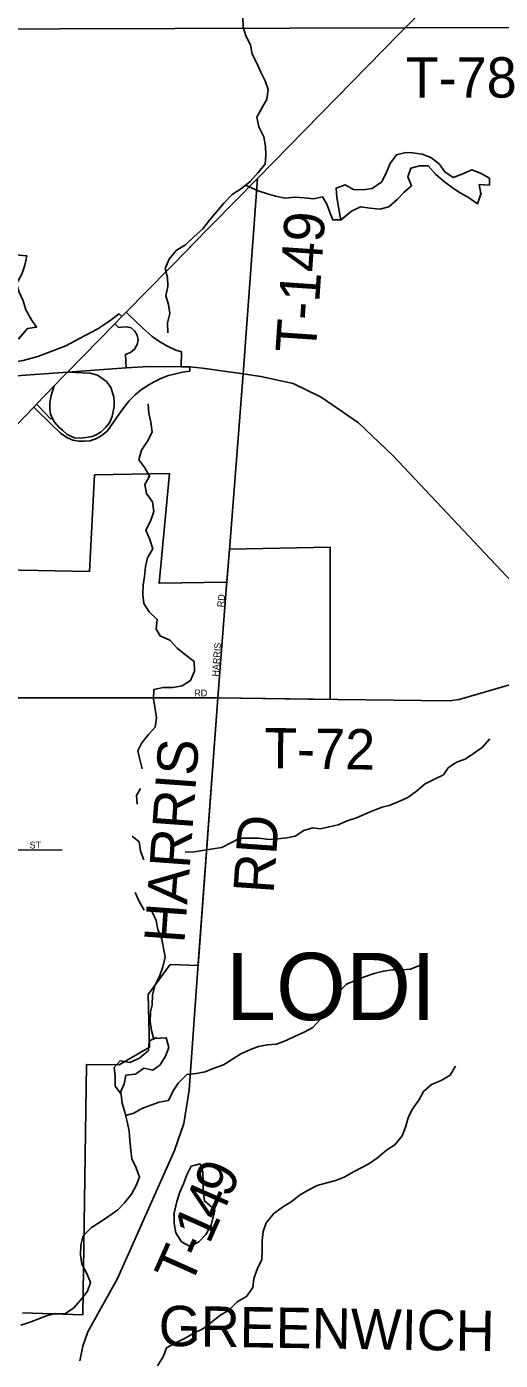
# Model space of a CAD drawing. Extents: x 1985906 to 2277390, y 930619 to 1324581.
# Drawn here: x 2107266 to 2110785, y 1102819 to 1112733 of the extents above; entities that cross this region are included whole.
import ezdxf

# ---------------------------------------------------------------- set-up
doc = ezdxf.new("R2010")
doc.units = 0
for name, color, linetype in [('GM_X_City_Street', 7, 'Continuous'), ('GM_X_City_Street_Text', 7, 'Continuous'), ('GM_X_Corporation', 7, 'Continuous'), ('GM_X_Corporation_Text', 7, 'Continuous'), ('GM_X_County_Road', 7, 'Continuous'), ('GM_X_County_Road_Text', 7, 'Continuous'), ('GM_X_Interchange_Ramps', 7, 'Continuous'), ('GM_X_Minor_Lake', 7, 'Continuous'), ('GM_X_Minor_River', 7, 'Continuous'), ('GM_X_State_Route', 7, 'Continuous'), ('GM_X_Township_Road', 7, 'Continuous'), ('GM_X_Township_Road_Text', 7, 'Continuous'), ('GM_X_US_Route', 7, 'Continuous')]:
    doc.layers.add(name, color=color, linetype=linetype)

msp = doc.modelspace()

# ---------------------------------------------------------------- linework, layer by layer
at = {"layer": 'GM_X_City_Street'}
for points in [[(2108686.1, 1107743.1), (2108752, 1108580.9)], [(2106854.4, 1107744.7), (2108686.1, 1107743.1)], [(2105816.4, 1106274.2), (2105822.4, 1106388.5), (2105826.4, 1106430.6), (2105848.5, 1106460.6), (2106017, 1106600.8), (2106049.1, 1106616.8), (2106099.2, 1106618.8), (2107531.1, 1106611.3)]]:
    msp.add_lwpolyline(points, dxfattribs=at)
at = {"layer": 'GM_X_Corporation'}
msp.add_lwpolyline([(2106834.5, 1108699.8), (2107732.7, 1108684), (2107771.3, 1109401.2), (2108328.5, 1109410.8), (2108249.8, 1108595.8), (2108753.9, 1108604.5), (2108773.2, 1108849.8), (2109521.9, 1108862.7), (2109521.7, 1107732.4), (2108686.1, 1107743.1), (2108540.2, 1105753.8), (2108332.5, 1105762.2), (2108168.7, 1105539.2), (2108177.8, 1105146.7), (2107954, 1105015.8), (2107709.7, 1105019.2), (2107682.9, 1103156.3), (2107236.4, 1103173.1)], dxfattribs=at)
at = {"layer": 'GM_X_County_Road'}
msp.add_lwpolyline([(2100720.2, 1112676.7), (2101399.8, 1112691.3), (2102090.2, 1112703.5), (2103621.7, 1112702.2), (2104296.1, 1112708.3), (2104940.4, 1112710.2), (2110078.2, 1112724.1)], dxfattribs=at)
at = {"layer": 'GM_X_Interchange_Ramps'}
for points in [[(2107974.3, 1110577.7), (2107954, 1110597.6), (2107869.4, 1110536.2), (2107794.8, 1110487.1), (2107694.8, 1110434.3), (2107558.4, 1110361.5), (2107452.9, 1110319.7), (2107349.2, 1110281.5), (2107240, 1110252.3), (2107180, 1110240.4), (2107187.4, 1110137.9)], [(2108414, 1110204.4), (2108415.6, 1110315.9), (2108373.9, 1110328.6), (2108311.9, 1110357.3), (2108255.1, 1110390.1), (2108199.6, 1110430.2), (2108128, 1110494.8), (2108025.1, 1110590.2), (2108005.5, 1110609.5)], [(2107920.9, 1110523.2), (2107947.9, 1110496.8), (2107973.3, 1110500.2), (2108010.5, 1110502.6), (2108043.3, 1110493.2), (2108070.6, 1110470.4), (2108088.1, 1110439.3), (2108095.5, 1110405), (2108087.5, 1110369.7), (2108067.8, 1110334.9), (2108037.2, 1110310.9), (2107999.3, 1110294.7), (2108006.3, 1110196.6)], [(2107318.4, 1109905.6), (2107336.4, 1109888.2), (2107446.2, 1109780.3), (2107518.8, 1109711.3), (2107564.6, 1109679.3), (2107608.3, 1109660.1), (2107652.6, 1109652.5), (2107693.9, 1109651.3), (2107737.5, 1109655.2), (2107785.4, 1109672.4), (2107826.4, 1109696.9), (2107865.7, 1109728.9), (2107955.6, 1109858.3), (2107998.6, 1109913.8), (2108028.4, 1109951.7), (2108073.3, 1109997.1), (2108118.6, 1110036), (2108173.2, 1110070.3), (2108213, 1110093.4), (2108263, 1110118.4), (2108319.7, 1110140), (2108371.7, 1110152.2), (2108425, 1110165.8), (2108478.1, 1110172.6), (2108478.5, 1110203.5)], [(2107456.2, 1109824.2), (2107446, 1109816.2), (2107355.5, 1109910), (2107338.4, 1109926.4)]]:
    msp.add_lwpolyline(points, dxfattribs=at)
at = {"layer": 'GM_X_Minor_Lake'}
for points in [[(2110641.6, 1111490.3), (2110628.3, 1111559.5), (2110704.6, 1111555.7), (2110704.4, 1111605.8), (2110638, 1111643.8), (2110573.6, 1111667.6), (2110507.4, 1111639.4), (2110435.2, 1111611.1), (2110372.8, 1111653.1), (2110330.4, 1111713.1), (2110267.9, 1111761.1), (2110203.5, 1111785), (2110133.2, 1111794.8), (2110082.9, 1111796.7), (2110014.7, 1111780.4), (2109966.7, 1111716.1), (2109940.8, 1111651.9), (2109904.9, 1111579.6), (2109832.8, 1111529.2), (2109766.5, 1111519.1), (2109694.2, 1111522.9), (2109631.8, 1111556.8), (2109565.6, 1111532.5), (2109569.9, 1111462.4), (2109582.2, 1111390.2), (2109599.2, 1111295.5)], [(2110641, 1111493.8), (2110628.3, 1111559.5), (2110704.6, 1111555.7), (2110704.4, 1111605.8), (2110638, 1111643.8), (2110573.6, 1111667.6), (2110507.4, 1111639.4), (2110435.2, 1111611.1), (2110372.8, 1111653.1), (2110330.4, 1111713.1), (2110267.9, 1111761.1), (2110203.5, 1111785), (2110133.2, 1111794.8), (2110082.9, 1111796.7), (2110014.7, 1111780.4), (2109966.7, 1111716.1), (2109940.8, 1111651.9), (2109904.9, 1111579.6), (2109832.8, 1111529.2), (2109766.5, 1111519.1), (2109694.2, 1111522.9), (2109631.8, 1111556.8), (2109565.6, 1111532.5), (2109569.9, 1111462.4), (2109582.2, 1111390.2), (2109599.2, 1111295.2)], [(2109599.2, 1111295.5), (2109678.7, 1111360.4), (2109746.9, 1111392.6), (2109819.3, 1111384.8), (2109889.6, 1111377), (2109957.9, 1111393.2), (2110020, 1111447.5), (2110072, 1111503.8), (2110126, 1111550.1), (2110097.7, 1111616.2), (2110121.5, 1111680.4), (2110185.8, 1111698.7), (2110250, 1111698.8), (2110306.5, 1111632.8), (2110371, 1111578.9), (2110437.5, 1111530.9), (2110487.9, 1111496.9), (2110548.3, 1111463), (2110614.7, 1111417.1), (2110641.6, 1111490.3)], [(2109601.4, 1111297.4), (2109678.7, 1111360.4), (2109746.9, 1111392.6), (2109819.3, 1111384.8), (2109889.6, 1111377), (2109957.9, 1111393.2), (2110020, 1111447.5), (2110072, 1111503.8), (2110126, 1111550.1), (2110097.7, 1111616.2), (2110121.5, 1111680.4), (2110185.8, 1111698.7), (2110250, 1111698.8), (2110306.5, 1111632.8), (2110371, 1111578.9), (2110437.5, 1111530.9), (2110487.9, 1111496.9), (2110548.3, 1111463), (2110614.7, 1111417.1), (2110643.1, 1111494.4)], [(2107204.3, 1110411), (2107273.2, 1110489.4), (2107339.5, 1110499.6), (2107303.1, 1110553.7), (2107260.6, 1110627.8), (2107240.3, 1110693.9), (2107209.9, 1110760), (2107191.6, 1110822.1), (2107229.5, 1110892.4), (2107251.4, 1110960.7), (2107267.2, 1111028.9), (2107180.5, 1111036.5)], [(2107204.4, 1110411.2), (2107273.2, 1110489.4), (2107339.5, 1110499.6), (2107303.1, 1110553.7), (2107260.6, 1110627.8), (2107240.3, 1110693.9), (2107209.9, 1110760), (2107191.6, 1110822.1), (2107229.5, 1110892.4), (2107251.4, 1110960.7), (2107267.2, 1111028.9), (2107185.4, 1111036)], [(2107965.6, 1104803.8), (2107923.2, 1104857.3), (2107924.9, 1104929.5), (2107916.6, 1104995.6), (2107960.6, 1105045.9), (2108033, 1105034.1), (2108105.2, 1105066.4), (2108171.3, 1105122.7), (2108177.1, 1105192.9), (2108233.2, 1105219.1)], [(2108218, 1105212), (2108177.1, 1105192.9), (2108171.3, 1105122.7), (2108105.2, 1105066.4), (2108033, 1105034.1), (2107960.6, 1105045.9), (2107916.6, 1104995.6), (2107924.9, 1104929.5), (2107923.2, 1104857.3), (2107962, 1104808.3)], [(2108205.4, 1105211.2), (2108303.5, 1105217.3), (2108321.9, 1105145.2), (2108298, 1105078.9), (2108258.1, 1105016.6), (2108204, 1104976.4), (2108135.6, 1104990.2), (2108075.5, 1104945.9), (2108003.2, 1104939.7), (2107989.4, 1104875.5), (2107961.5, 1104807.2)], [(2107962, 1104808.3), (2107989.4, 1104875.5), (2108003.2, 1104939.7), (2108075.5, 1104945.9), (2108135.6, 1104990.2), (2108204, 1104976.4), (2108258.1, 1105016.6), (2108298, 1105078.9), (2108321.9, 1105145.2), (2108303.5, 1105217.3), (2108218, 1105212)], [(2108662.8, 1103940.6), (2108587.3, 1104004.6), (2108577, 1104076.8), (2108576.8, 1104145), (2108574.5, 1104217.2), (2108554.2, 1104279.3), (2108487.9, 1104263.1), (2108456, 1104198.8), (2108430.2, 1104130.6), (2108404.3, 1104068.3), (2108382.4, 1104000.1), (2108359.9, 1103901.4)], [(2108665.4, 1103938.3), (2108587.3, 1104004.6), (2108577, 1104076.8), (2108576.8, 1104145), (2108574.5, 1104217.2), (2108554.2, 1104279.3), (2108487.9, 1104263.1), (2108456, 1104198.8), (2108430.2, 1104130.6), (2108404.3, 1104068.3), (2108382.4, 1104000.1), (2108362.9, 1103914.5)], [(2108362.9, 1103914.5), (2108361, 1103835.5), (2108373.3, 1103767.4), (2108415.7, 1103699.3), (2108482.1, 1103665.4), (2108544.3, 1103699.6), (2108598.3, 1103753.9), (2108638.2, 1103824.3), (2108665.4, 1103938.3)], [(2108362.7, 1103907.8), (2108361, 1103835.5), (2108373.3, 1103767.4), (2108415.7, 1103699.3), (2108482.1, 1103665.4), (2108544.3, 1103699.6), (2108598.3, 1103753.9), (2108638.2, 1103824.3), (2108664.9, 1103936.2)]]:
    msp.add_lwpolyline(points, dxfattribs=at)
at = {"layer": 'GM_X_Minor_River'}
for points in [[(2108871.7, 1112800.1), (2108874, 1112729.9), (2108894.3, 1112665.8), (2108928.7, 1112597.7), (2108941.1, 1112529.6), (2108975.5, 1112461.5), (2109005.8, 1112395.4), (2109038.2, 1112329.3), (2109060.6, 1112265.2), (2109050.8, 1112194.9), (2109014.9, 1112132.7), (2108977, 1112060.4), (2108991.3, 1111988.2), (2109027.8, 1111914.1), (2109040.1, 1111844), (2109044.3, 1111777.8), (2109038.6, 1111709.6), (2108982.6, 1111645.3), (2108926.5, 1111582.9), (2108862.4, 1111530.6), (2108792.3, 1111484.3), (2108732.3, 1111422), (2108624.3, 1111293.3), (2108574.3, 1111229), (2108510.2, 1111172.7), (2108446.1, 1111112.3), (2108378, 1111068), (2108326, 1111003.7), (2108294.1, 1110935.4), (2108312.5, 1110869.3), (2108314.7, 1110801.1), (2108300.9, 1110732.9), (2108319.2, 1110666.8), (2108329.5, 1110600.6), (2108313.7, 1110530.4), (2108314, 1110458.2)], [(2109604.7, 1111296), (2109540.4, 1111295.8), (2109522.1, 1111345.9), (2109495.7, 1111414), (2109463.4, 1111468.1), (2109397.1, 1111451.9), (2109326.8, 1111461.7), (2109258.5, 1111465.5), (2109186.2, 1111457.3), (2109115.8, 1111473.2), (2109055.5, 1111491.1), (2108987.1, 1111512.9), (2108891.2, 1111554.2)], [(2108169.3, 1109930.3), (2108173.6, 1109858.1), (2108187.9, 1109792), (2108198.2, 1109719.8), (2108164.3, 1109651.5), (2108118.4, 1109585.2), (2108098.6, 1109512.9), (2108145, 1109452.9), (2108179.4, 1109390.8), (2108143.5, 1109328.6), (2108155.8, 1109262.4), (2108202.2, 1109200.4), (2108210.5, 1109128.2), (2108186.7, 1109055.9), (2108152.8, 1108989.6), (2108181.1, 1108921.5), (2108203.5, 1108851.4), (2108163.6, 1108785.1), (2108149.8, 1108718.9), (2108142, 1108646.6), (2108132.2, 1108580.4), (2108128.4, 1108512.2), (2108136.7, 1108446.1), (2108177.1, 1108384), (2108235.6, 1108326), (2108227.9, 1108253.8), (2108258.2, 1108203.7), (2108330.6, 1108171.8), (2108385.1, 1108113.8), (2108449.6, 1108061.8), (2108510, 1108013.8), (2108514.3, 1107941.6), (2108482.4, 1107873.4), (2108420.3, 1107833.1), (2108352, 1107820.9), (2108279.7, 1107820.7), (2108211.5, 1107806.4), (2108207.7, 1107734.2), (2108222, 1107662.1), (2108230.3, 1107593.9), (2108220.5, 1107525.7), (2108172.5, 1107471.4), (2108122.5, 1107409.1), (2108092.6, 1107350.8), (2108106.9, 1107284.7), (2108123.3, 1107216.5)], [(2110708, 1107438.2), (2110652, 1107377.9), (2110585.9, 1107329.6), (2110523.8, 1107287.3), (2110459.5, 1107265), (2110397.4, 1107222.7), (2110363.5, 1107172.5), (2110297.3, 1107138.2), (2110227.1, 1107103.9), (2110163, 1107049.6), (2110098.9, 1107003.3), (2110026.7, 1106971), (2109958.5, 1106942.7), (2109908.3, 1106930.6), (2109844.1, 1106906.3), (2109779.9, 1106878.1), (2109715.8, 1106851.8), (2109647.5, 1106829.6), (2109581.4, 1106799.3), (2109513.1, 1106785.1), (2109446.9, 1106770.9), (2109392.6, 1106776.7), (2109326.4, 1106758.5), (2109260.2, 1106716.2), (2109198, 1106702), (2109131.7, 1106695.8), (2109065.4, 1106691.6), (2108993.1, 1106699.4), (2108922.8, 1106701.2), (2108850.5, 1106701.1), (2108784.3, 1106666.8), (2108716.1, 1106630.5), (2108649.8, 1106620.3), (2108513.3, 1106599.8), (2108445, 1106597.6)], [(2108111.8, 1107070.1), (2108081.8, 1107017.9), (2108088.1, 1106953.7)], [(2108050.8, 1106714.9), (2108103.2, 1106672.9), (2108111.5, 1106604.8), (2108137.9, 1106538.6)], [(2108072.5, 1106297.8), (2108098.8, 1106235.7), (2108139.3, 1106165.6)], [(2108195.5, 1106157.7), (2108227.9, 1106089.6), (2108240.3, 1106021.4), (2108270.7, 1105949.3), (2108295.3, 1105817), (2108277.5, 1105744.8), (2108255.6, 1105678.5), (2108217.7, 1105606.2), (2108201.9, 1105533.9), (2108198.2, 1105459.7), (2108186.3, 1105409.6), (2108184.6, 1105337.3), (2108192.8, 1105271.2), (2108207.6, 1105213.4)], [(2110184, 1105754), (2110117.8, 1105727.7), (2110055.5, 1105721.5), (2109985.2, 1105721.3), (2109916.9, 1105713.1), (2109848.7, 1105694.9), (2109776.4, 1105670.6), (2109706.2, 1105642.4), (2109642, 1105616.1), (2109580, 1105553.8), (2109534, 1105487.4), (2109492.1, 1105415.1), (2109446.2, 1105352.8), (2109392.1, 1105292.5), (2109328, 1105258.2), (2109261.8, 1105230), (2109193.6, 1105197.7), (2109123.4, 1105169.4), (2109055.1, 1105165.2), (2108988.9, 1105151), (2108928.7, 1105128.8), (2108858.5, 1105096.5), (2108796.3, 1105058.2), (2108728.2, 1105015.9), (2108652, 1104989.6), (2108591.8, 1104963.4), (2108525.5, 1104951.2), (2108457.3, 1104943), (2108391.2, 1104878.6), (2108351.3, 1104816.3), (2108319.4, 1104750), (2108251.1, 1104737.8), (2108188.9, 1104715.6), (2108122.7, 1104691.3), (2108062.6, 1104657.1), (2108000.5, 1104638.1)], [(2110452, 1105004.6), (2110412, 1104938.3), (2110345.9, 1104898), (2110273.7, 1104869.7), (2110213.6, 1104817.4), (2110179.7, 1104753.1), (2110129.7, 1104684.8), (2110099.8, 1104620.5), (2110082, 1104552.3), (2110056.1, 1104488), (2110002.1, 1104421.7), (2109940, 1104381.4), (2109871.9, 1104325.1), (2109807.8, 1104278.8), (2109757.6, 1104252.5), (2109693.5, 1104220.3), (2109629.3, 1104182), (2109563.1, 1104155.7), (2109496.9, 1104139.5), (2109424.7, 1104119.2), (2109358.5, 1104085), (2109298.4, 1104048.7), (2109230.3, 1103996.4), (2109168.1, 1103958.1), (2109102, 1103909.8), (2109046, 1103841.4), (2109024.1, 1103777.2), (2109016.4, 1103709), (2109016.6, 1103636.8), (2109012.9, 1103568.6), (2108981, 1103502.3), (2108953.1, 1103428), (2108945.4, 1103359.8), (2108899.4, 1103293.5), (2108829.2, 1103255.1), (2108767.2, 1103192.8), (2108701, 1103152.5), (2108636.9, 1103100.2), (2108574.8, 1103053.9), (2108508.7, 1103021.6), (2108444.5, 1102983.3), (2108374.3, 1102949), (2108306.2, 1102912.8), (2108282.3, 1102850.5), (2108238.4, 1102778.2)], [(2107965.6, 1104812.5), (2107975.9, 1104731.1), (2107996.2, 1104664.9), (2108012.6, 1104594.8), (2108026.9, 1104522.6), (2108033.2, 1104454.4), (2108039.5, 1104382.2), (2108047.8, 1104316.1), (2108080.2, 1104250), (2108104.5, 1104181.8), (2108078.6, 1104117.6), (2108044.7, 1104053.3), (2107992.7, 1103989), (2107942.7, 1103936.7), (2107876.6, 1103890.4), (2107814.5, 1103848.1), (2107748.3, 1103805.8), (2107686.3, 1103743.4), (2107668.5, 1103675.2), (2107666.7, 1103603), (2107677, 1103532.8), (2107713.5, 1103464.7), (2107739.8, 1103398.6), (2107718, 1103332.3), (2107668, 1103268), (2107614, 1103207.7), (2107549.8, 1103165.4), (2107477.5, 1103167.2), (2107413.3, 1103151), (2107349.1, 1103124.8), (2107284.9, 1103100.5), (2107222.7, 1103080.3)]]:
    msp.add_lwpolyline(points, dxfattribs=at)
at = {"layer": 'GM_X_State_Route'}
msp.add_lwpolyline([(2106189.3, 1108732.9), (2106550, 1109107.3), (2107318.4, 1109905.6), (2107338.4, 1109926.4), (2107469.8, 1110062.9)], dxfattribs=at)
at = {"layer": 'GM_X_Township_Road'}
for points in [[(2110078.2, 1112724.1), (2112864.3, 1112725.6), (2112895.4, 1112715.1)], [(2108772.6, 1108842.7), (2108875.6, 1110151.7), (2108981.3, 1111605.2)], [(2108752, 1108580.9), (2108772.6, 1108842.7)], [(2109577.9, 1107731.7), (2110407.9, 1107721), (2110480.1, 1107731.6), (2111433.1, 1108007.9), (2112636.2, 1108357.2), (2112881.6, 1108428.5), (2112912.1, 1108432.1), (2112951.9, 1108437), (2113076.7, 1108435.3)], [(2108541.3, 1105768.8), (2108686.1, 1107743.1)], [(2108686.1, 1107743.1), (2109577.9, 1107731.7)], [(2107661.4, 1102816.3), (2107682.7, 1102924.8), (2107720.1, 1103031.4), (2107942.2, 1103428.2), (2108365.1, 1104378.2), (2108434, 1104579.3), (2108472.4, 1104828.4), (2108541.3, 1105768.8), (2108541.3, 1105768.8)]]:
    msp.add_lwpolyline(points, dxfattribs=at)
at = {"layer": 'GM_X_US_Route'}
for points in [[(2108478.2, 1111091.8), (2108483.7, 1111097.5), (2108981.3, 1111605.2), (2110033.6, 1112678.9), (2110078.2, 1112724.1), (2112980.4, 1115674.7), (2113389.1, 1116084.6), (2117701, 1120584.3), (2119807.9, 1122792.3), (2120304.7, 1123312.9), (2122862.5, 1125977.7), (2123167.1, 1126295)], [(2107545, 1110139.6), (2107570.2, 1110165.4), (2107920.9, 1110523.2), (2107974.3, 1110577.7), (2108005.5, 1110609.5), (2108478.2, 1111091.8)], [(2101613.5, 1109753), (2104936.7, 1109981.2), (2106522.3, 1110090.1), (2107187.4, 1110137.9), (2107570.2, 1110165.4)], [(2107570.2, 1110165.4), (2107739, 1110156.2), (2107792.8, 1110141.5), (2107859.7, 1110094.2), (2107891.2, 1110051.1), (2107912.8, 1109981.7), (2107916, 1109940.9), (2107916, 1109909.9), (2107902.6, 1109835.6), (2107881.3, 1109789.1), (2107855.2, 1109755.6), (2107820.6, 1109722.1), (2107783.4, 1109698.5), (2107752, 1109686.2), (2107707.5, 1109678.9), (2107664.3, 1109674.8), (2107621.8, 1109677.2), (2107594.1, 1109688.7), (2107568, 1109701.8), (2107532.1, 1109732.8), (2107505.2, 1109756.4), (2107472.7, 1109793.2), (2107456.2, 1109824.2), (2107444.3, 1109852.8), (2107439.1, 1109894.4), (2107437.4, 1109938.5), (2107448, 1109992.3), (2107469.8, 1110062.9)], [(2107469.8, 1110062.9), (2107542.2, 1110136.8), (2107545, 1110139.6)], [(2107570.2, 1110165.4), (2108006.3, 1110196.6), (2108174.8, 1110206), (2108414, 1110204.4), (2108478.5, 1110203.5), (2108572.9, 1110194.6), (2108875.6, 1110151.7), (2109006.1, 1110133.2), (2109247.3, 1110080), (2109454.6, 1109978.5), (2109730.6, 1109789), (2109988.8, 1109543.3), (2111433.1, 1108007.9)]]:
    msp.add_lwpolyline(points, dxfattribs=at)

# ---------------------------------------------------------------- texts
at = {"layer": 'GM_X_City_Street_Text'}
for s, rotation, p in [('RD', 83.98769, (2108730.8, 1108415.1)), ('HARRIS', 85.51559, (2108691.2, 1107900.1)), ('RD', 0.00001, (2108511.3, 1107754.8)), ('ST', 0.00001, (2107288.1, 1106624))]:
    msp.add_text(s, height=50, rotation=rotation, dxfattribs=at).set_placement(p)
at = {"layer": 'GM_X_Corporation_Text'}
msp.add_text('LODI', height=500, rotation=0.00001, dxfattribs=at).set_placement((2108746.7, 1105348.1))
at = {"layer": 'GM_X_County_Road_Text'}
msp.add_text('GREENWICH', height=300, rotation=359.08646, dxfattribs=at).set_placement((2108245.2, 1102926.6))
at = {"layer": 'GM_X_Township_Road_Text'}
for s, rotation, p in [('T-78', 0.00001, (2110082.1, 1112205.5)), ('T-149', 86.07407, (2109413.6, 1110301.3)), ('T-72', 359.29172, (2109028.5, 1107220.3)), ('HARRIS', 85.87445, (2108437.6, 1105914.7)), ('RD', 86.05513, (2109100.6, 1106284.3)), ('9', 66.34245, (2108773.4, 1104015)), ('4', 66.07417, (2108697.8, 1103844.7)), ('1', 66.00398, (2108622.5, 1103675.4)), ('T', 65.98093, (2108480.9, 1103357.8)), ('-', 65.98274, (2108572.3, 1103562.8))]:
    msp.add_text(s, height=300, rotation=rotation, dxfattribs=at).set_placement(p)

doc.saveas('drawing.dxf')
